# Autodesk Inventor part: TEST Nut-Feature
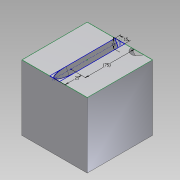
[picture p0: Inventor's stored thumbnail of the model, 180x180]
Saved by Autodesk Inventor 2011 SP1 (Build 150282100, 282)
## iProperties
Created: 2010-09
Part Number: TEST Nut-Feature
Document SubType Name: Modeling
Designer: schmitt
Density: 1 g/cm^3
Author: schmitt
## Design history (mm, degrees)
sketch "Skizze1"
  geometry: L1 (-50, -50)-(50, -50); L2 (50, -50)-(50, 50); L3 (50, 50)-(-50, 50); L4 (-50, 50)-(-50, -50); 3 further points
  constraints: 8 end point, 2 midpoint, 2 parallel, 2 perpendicular, 1 horizontal, 1 horizontal alignment, 1 vertical alignment
  dimensions: "d0" = 100 distance of L2.end L3.end
extrude "Extrusion1" new body sketch "Skizze1" distance "d1" = 100; taper "d2" = 0 deg
workplane "Arbeitsebene4"
  workplane "Arbeitsebene3"
sketch "Skizze28"
  geometry: L1 (50, 85)-(-25, 85); L2 (-25, 85)-(-25, 100); L3 (-25, 115)-(50, 115); L4 (50, 100)-(-50, 100); L5 (-50, 96.973)-(-50, 103.027); L6 (-50, 100)-(-80.241, 100); L7 (-16.332, 85)-(-33.668, 85); A1 r 13.427 centre (-36.573, 100) between (-49.787, 102.383) and (-49.787, 97.617); A2 r 69.898 centre (-25, 154.898) between (-31.901, 85.341) and (-18.099, 85.341); 3 further points
  constraints: 14 end point, 4 midpoint, 3 perpendicular, 2 centre point, 2 horizontal, 2 parallel, 2 point on circle, 1 coincident, 1 collinear, 1 point on line, 1 vertical, 6 other
revolve "Umdrehung8" stored, may be unused: angle "d89" = 180 deg
feature "Sweeping1" dims "d90" = 0
sketch "Skizze4"
  geometry: L1 (0, 0)-(0, 100); L2 (7.5, 0)-(0, 15); L3 (-7.5, 0)-(0, 15); L4 (7.5, 0)-(-7.5, 0)
  constraints: 8 end point, 1 point on line
  dimensions: "d87" = 15 distance of L2.end L1.start
extrude "Extrusion8" cut sketch "Skizze4" stored distance "d82" = 10; taper "d83" = 0 deg
revolve "Umdrehung7" stored, may be unused: angle "d84" = 180 deg
sketch "Skizze3" dims "Nutführungslänge" = 25
  geometry: L1 (79.441, -100)-(79.441, 0) reference; L2 (-20.559, -100)-(79.441, -100) reference; L3 (-20.559, 0)-(-20.559, -100) reference; L4 (79.441, 0)-(-20.559, 0) reference; L5 (29.441, 0)-(29.441, -100); L6 (21.941, 0)-(21.941, -75); L7 (36.941, 0)-(36.941, -75); L8 (21.941, 0)-(36.941, 0); L9 (21.941, -75)-(21.941, -100); L10 (21.941, -100)-(36.941, -100); L11 (36.941, -75)-(36.941, -100); 2 further points; 1 other entity
  constraints: 15 end point, 4 symmetric about line, 4 vertical, 3 point on line, 2 collinear, 2 parallel, 2 perpendicular, 1 midpoint, 5 other
  dimensions: "Nutbreite" = 15 distance between parallel lines of L6 L7; "d88" = 75 distance from line of L4 point (29.441, -75) (derived)
extrude "Extrusion9" join sketch "Skizze3" distance "d85" = 15; taper "d86" = 0 deg
node "Volumenkörper1"
sketch "Skizze2"
  geometry: L1 (79.441, -100)-(20.559, -100); L2 (0, -100)-(100, -100) reference; L3 (100, 0)-(0, 0) reference; L4 (50, 0)-(50, -100); L5 (86.135, -100)-(76.882, -87.756); L6 (76.882, -87.756)-(76.882, -100); 1 further point
  constraints: 8 end point, 4 midpoint, 2 point on line, 1 coincident, 1 horizontal, 1 perpendicular
sketch "Skizze5"
  geometry: L1 (50, 85)-(-35, 85); L2 (-35, 85)-(-50, 85); L3 (-50, 85)-(-50, 100); L4 (-50, 100)-(50, 100); A1 r 15 centre (-35, 100) between (-50, 100) and (-35, 85); 2 further points
  constraints: 8 end point, 3 tangent, 2 point on circle, 1 centre point, 1 coincident, 1 collinear, 1 horizontal, 1 perpendicular
  dimensions: "d71" = 30 diameter of A1
node "Projizierte Kontur1"
other parameters: "d29" = 90 deg
